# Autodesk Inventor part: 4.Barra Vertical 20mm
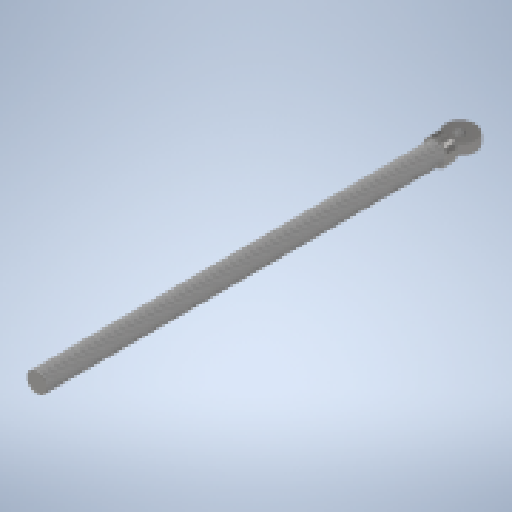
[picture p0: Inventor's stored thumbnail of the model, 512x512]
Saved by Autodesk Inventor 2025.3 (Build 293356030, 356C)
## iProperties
Created: 2025-10
Part Number: 4.Barra Vertical 20mm
Material: Genérico
Document SubType Name: Modeling
Designer: User
Density: 1 g/cm^3
Appearance: Valor por defecto
Author: User
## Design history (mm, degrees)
sketch "Boceto1"
  geometry: C1 r 10 at (0, 0); 1 further point
  constraints: 1 centre point
  dimensions: "d0" = 0 distance of point (0, 0) C1.centre; "d1" = 0 distance of point (0, 0) C1.centre; "d2" = 20 diameter of C1
extrude "Extrusión1" new body sketch "Boceto1" distance "d3" = 450; taper "d4" = 0 deg
node "Plano de trabajo1"
sketch "Boceto4"
  geometry: C1 r 10 at (0, 0) reference; C2 r 12.5 at (0, 0); 1 further point
  constraints: 1 centre point
  dimensions: "d6" = 0 distance of point (0, 0) C2.centre; "d7" = 0 distance of C2.centre point (0, 0); "d8" = 25 diameter of C2
extrude "Extrusión2" join sketch "Boceto4" distance "d9" = 10; taper "d10" = 0 deg
sketch "Boceto5"
  geometry: L1 (-12.5, -10)-(12.5, -10) reference; L2 (-12.5, 0)-(-12.5, -10) reference; C1 r 15 at (0, -25); 2 further points
  constraints: 1 centre point, 1 midpoint
  dimensions: "d11" = 15 distance from line of C1.centre L1; "d13" = 30 diameter of C1; "d14" = 0 horizontal distance of C1.centre point (0, -10)
extrude "Extrusión3" join sketch "Boceto5" stored distance "d15" = 10; taper "d16" = 0 deg
sketch "Boceto6"
  geometry: 4 further points
  constraints: 1 vertical alignment
  dimensions: "d17" = 0 distance of point (0, 0) point (0, 0); "d18" = 0 distance of point (0, 0) point (0, 0)
hole "Agujero1" sketch "Boceto6" at (0, 0) diameter "d19" = 10.106; stored, may be unused: countersink angle "d23" = 90 deg, drill point angle "d25" = 118 deg; dims "d20" = 24, "d21" = 4, "d22" = 2, "d24" = 8
feature "Rosca1" dims "d26" = 500, "d27" = 0
node "Sólido1"
node "Acabados"
node "Finish1" dims "Finish1_Area" = 428.04023
